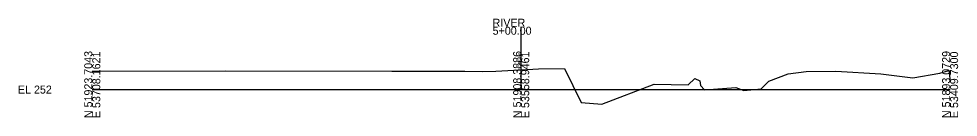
# Model space of a CAD drawing. Extents: x 5628 to 5956, y 92469 to 104012.
# Drawn here: x 5627.6 to 5956.2, y 94468.9 to 94503.4 of the extents above; entities that cross this region are included whole.
import ezdxf

# ---------------------------------------------------------------- set-up
doc = ezdxf.new("R2010")
doc.units = 0
for name, color, linetype in [('Level 10', 7, 'Continuous'), ('Level 60', 7, 'Continuous'), ('Level 63', 7, 'Continuous')]:
    doc.layers.add(name, color=color, linetype=linetype)

msp = doc.modelspace()

# ---------------------------------------------------------------- linework, layer by layer
at = {"layer": 'Level 60'}
for p, q in [((5653.34, 94485.01), (5700.01, 94485.12)), ((5700.01, 94485.12), (5758.07, 94485.01)), ((5758.07, 94485.01), (5783.62, 94485.04)), ((5783.62, 94485.04), (5789.98, 94484.96)), ((5789.98, 94484.96), (5794.5, 94485.07)), ((5794.5, 94485.07), (5800.78, 94485.39)), ((5800.78, 94485.39), (5803.34, 94485.52)), ((5803.34, 94485.52), (5809.38, 94485.83)), ((5809.38, 94485.83), (5818.44, 94485.93)), ((5818.44, 94485.93), (5824.33, 94474.08)), ((5889.98, 94481.53), (5896.67, 94484.14)), ((5896.67, 94484.14), (5903.03, 94484.98)), ((5903.03, 94484.98), (5913.36, 94485.03)), ((5913.36, 94485.03), (5929.15, 94484.12)), ((5929.15, 94484.12), (5940.32, 94482.76)), ((5940.32, 94482.76), (5949.72, 94484.3)), ((5949.72, 94484.3), (5952.88, 94485.28)), ((5952.88, 94485.28), (5953.34, 94481.54)), ((5831.56, 94473.49), (5849.79, 94480.53)), ((5849.79, 94480.53), (5861.68, 94480.21)), ((5861.68, 94480.21), (5864.09, 94482.46)), ((5864.09, 94482.46), (5865.76, 94481.67)), ((5865.76, 94481.67), (5866, 94480.05)), ((5866, 94480.05), (5867.45, 94478.48)), ((5887.25, 94478.8), (5889.98, 94481.53)), ((5867.45, 94478.48), (5878.35, 94479.27)), ((5878.35, 94479.27), (5881.17, 94478.31)), ((5881.17, 94478.31), (5887.25, 94478.8)), ((5824.33, 94474.08), (5831.56, 94473.49))]:
    msp.add_line(p, q, dxfattribs=at)
at = {"layer": 'Level 63'}
for p, q in [((5803.34, 94478.6), (5803.34, 94500.61)), ((5653.34, 94478.6), (5803.34, 94478.6)), ((5803.34, 94478.6), (5953.34, 94478.6))]:
    msp.add_line(p, q, dxfattribs=at)

# ---------------------------------------------------------------- texts
at = {"layer": 'Level 10'}
msp.add_text('255.46', height=1.2, rotation=90, dxfattribs=at).set_placement((5803.54, 94486.52))
at = {"layer": 'Level 63'}
for s, p in [('RIVER', (5793.34, 94500.61)), ('5+00.00', (5793.34, 94497.81)), ('EL 252', (5627.33, 94477.2))]:
    msp.add_text(s, height=2.8, dxfattribs=at).set_placement(p)
for s, p in [('N 51923.7043', (5653.34, 94468.6)), ('E 53708.1621', (5656.14, 94468.6)), ('N 51908.3886', (5803.34, 94468.59)), ('E 53558.9461', (5806.14, 94468.6)), ('N 51893.0729', (5953.34, 94468.6)), ('E 53409.7300', (5956.14, 94468.6))]:
    msp.add_text(s, height=2.8, rotation=90, dxfattribs=at).set_placement(p)

doc.saveas('drawing.dxf')
